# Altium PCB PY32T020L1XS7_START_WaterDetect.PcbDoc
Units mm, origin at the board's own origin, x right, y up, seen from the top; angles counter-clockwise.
Board outline 16.38 x 40.16 mm, 2 copper layers (Top Layer, Bottom Layer); 15 components, 16 nets, 48 pads, 33 vias.
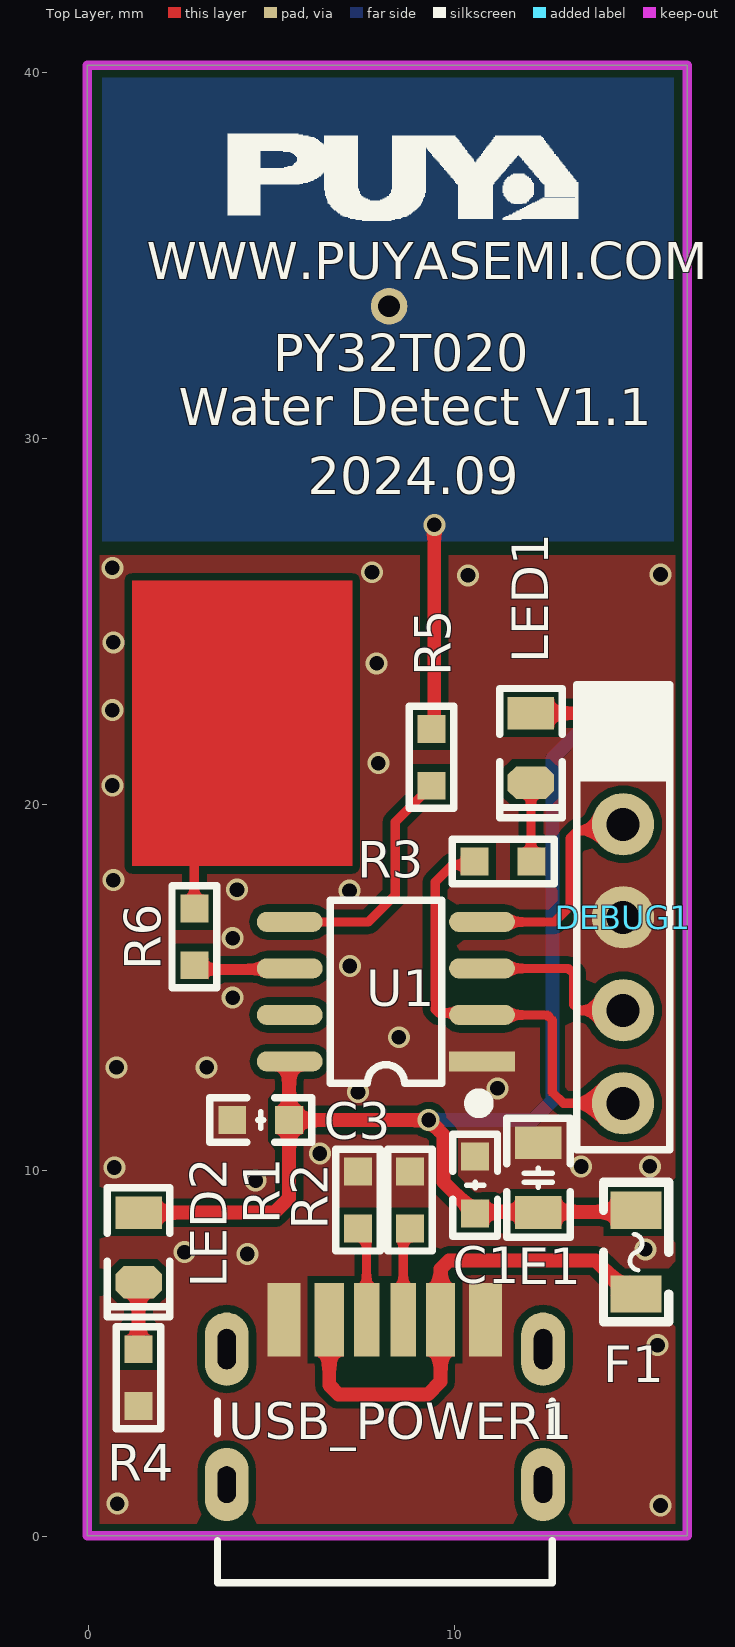
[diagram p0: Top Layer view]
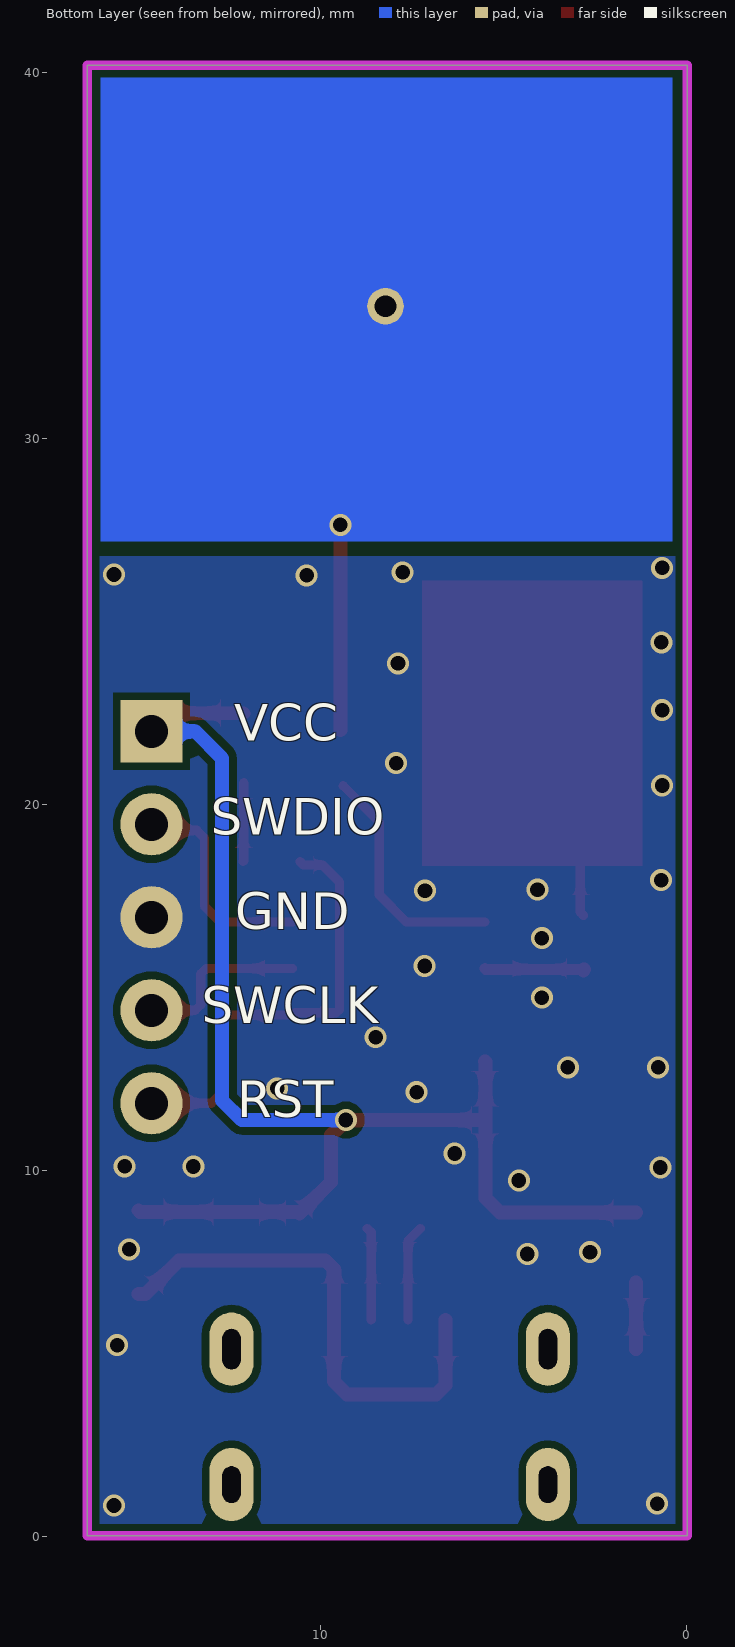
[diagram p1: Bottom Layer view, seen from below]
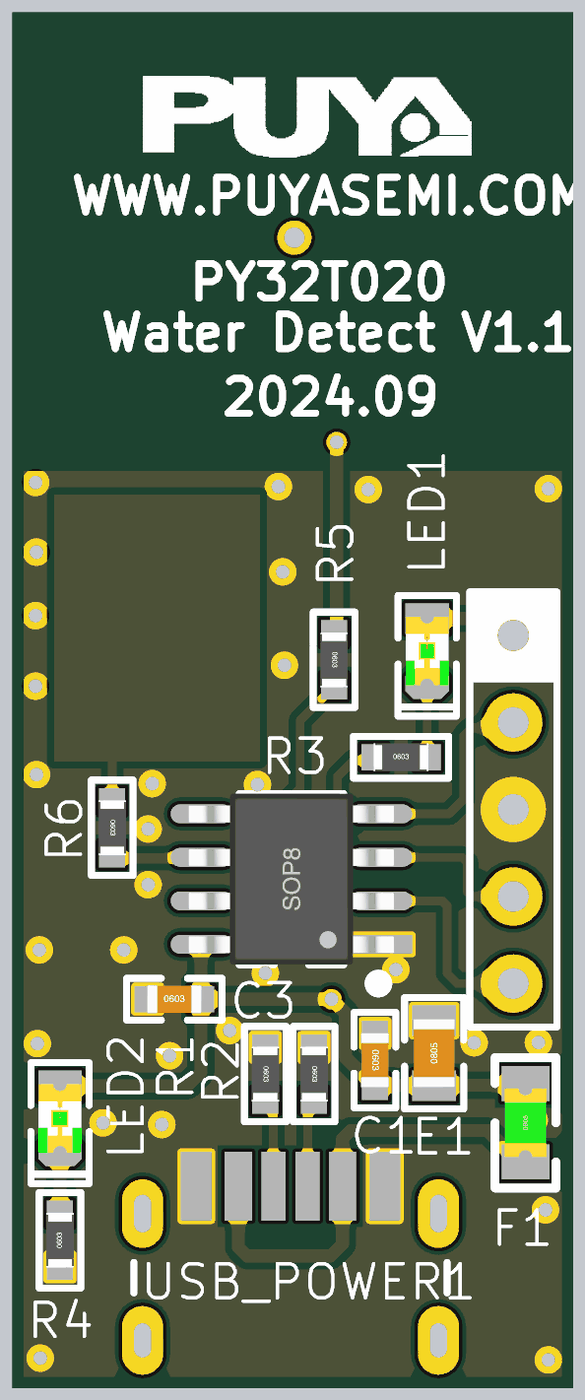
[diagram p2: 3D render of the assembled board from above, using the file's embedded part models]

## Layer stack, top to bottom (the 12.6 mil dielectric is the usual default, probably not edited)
Top Solder: solder mask 0.0102, Solder Resist, Dk 3.5
Top Layer: signal copper 0.0356
Dielectric 1: dielectric 0.32, FR-4, Dk 4.8
Bottom Layer: signal copper 0.0356
Bottom Solder: solder mask 0.0102, Solder Resist, Dk 3.5

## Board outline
-0.025,0.025 16.358,0.025 16.358,40.183 -0.025,40.183

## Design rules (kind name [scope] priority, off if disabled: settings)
Clearance Clearance_1 [All] p1: gap=0.2 ignorepadtopadclearanceinfootprint=FALSE
PlaneConnect [All] p1: planeconnectstyle=Direct reliefexpansion=0.508 reliefentries=4 reliefconductorwidth=0.254 reliefairgap=0.254
PolygonConnect [All] p1: connectstyle=Direct reliefconductorwidth=0.254 reliefentries=4 polygonreliefangle="90 Angle" airgapwidth=0.254
RoutingVias [All] p1: holewidth=0.711 width=1.27 viastyle="Through Hole" minholewidth=0.711 minwidth=1.27 maxholewidth=0.711 maxwidth=1.27
SolderMaskExpansion [All] p1: expansion=0.102 istentingtop=FALSE
SupplyNets "Schematic Supply Nets_2" [InNet('VCC')] p1: voltage=0.000
SupplyNets "Schematic Supply Nets_1" [InNet('GND')] p2: voltage=0.000
SupplyNets "Schematic Supply Nets" [InNet('VBUS')] p3: voltage=0.000
Width [All] p1: maxlimit=0.6 minlimit=0.254 preferedwidth=0.254
29 further rules are at their usual default settings.

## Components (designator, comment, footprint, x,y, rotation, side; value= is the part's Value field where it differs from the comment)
C1 "104" "C 0603_L" 10.566,9.601 r270 top
C3 "104" "C 0603_L" 4.709,11.379 r0 top
DEBUG1 "ISP" ISP_DIP_2.54_5P 14.605,21.996 r270 top
E1 "10uF/10V" "C 0805_L" 12.294,9.804 r90 top
F1 "500ma" "FU 0805" 14.961,7.772 r90 top
LED1 "红色" "LED 0805R" 12.09,21.539 r270 top
LED2 "红色" "LED 0805R" 1.372,7.899 r270 top
R1 "5.1K" "R 0603_L" 7.366,9.195 r270 top
R2 "5.1K" "R 0603_L" 8.788,9.195 r270 top
R3 "1K" "R 0603_L" 11.328,18.44 r0 top
R4 "1K" "R 0603_L" 1.372,4.343 r90 top
R5 "1K" "R 0603_L" 9.373,21.285 r270 top
R6 "1K" "R 0603_L" 2.896,16.383 r270 top
U1 "PY32T020L1XS7" SOP8_N 8.128,14.884 r180 top
USB_POWER1 "USB-C" USB-C/S_C 8.101,-1.128 r0 top

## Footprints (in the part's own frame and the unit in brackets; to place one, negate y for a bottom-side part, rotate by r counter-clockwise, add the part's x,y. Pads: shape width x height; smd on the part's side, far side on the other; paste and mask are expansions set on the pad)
"C 0603_L" [mil] "无极性贴片电容"
  rect 30x30 smd: 1(-30.59,0) 2(30.59,0)
  silkscreen extent -55,-24 55,24, body extent -31,-16 31,16, height 32
"C 0805_L" [mil] "无极性贴片电容"
  rect 35x50 smd: 1(-37.4,0) 2(37.4,0)
  silkscreen extent -64,-34 64,34, body extent -39,-24 39,24, height 20
"FU 0805" [mil] "贴片保险丝"
  rect 40x55 smd: 1(-45,0) 2(45,0)
  silkscreen extent -75,-35 75,35, body extent -39,-24 39,24, height 20
ISP_DIP_2.54_5P [mm] "5P 下载端口"
  rect 1.7x1.7 hole 0.9: 1(0,0)
  round 1.7 hole 0.9: 2(2.54,0) 3(5.08,0) 4(7.62,0) 5(10.16,0)
  silkscreen extent -1.27,-1.27 11.43,1.27
"LED 0805R" [mil] "红色0805LED"
  rect 35x50 smd: 1(-37.41,0)
  oct 35x50 smd: 2(37.4,0)
  silkscreen extent -64,-33 75,33, body extent -39,-25 39,25, height 32
"R 0603_L" [mil] "1/10W贴片电阻"
  rect 30x30 smd: 1(-30.59,0) 2(30.59,0)
  silkscreen extent -55,-24 55,24, body extent -31,-16 32,16, height 16
SOP8_N [mm] "5*6*1.8mm（长宽高）"
  rect 1.8x0.55 smd: 1(-2.625,1.905)
  oval 1.8x0.55 smd: 2(-2.625,0.635) 3(-2.625,-0.635) 4(-2.625,-1.905) 5(2.625,-1.905) 6(2.625,-0.635) 7(2.625,0.635) 8(2.625,1.905)
  silkscreen extent -2.69,-2.5 1.52,3.2, body extent -3,-2.5 3,2.5, height 1.9
USB-C/S_C [mm] "Type-C 6P母座"
  oval 1.2x2 hole 0.5 slot 1 at 90 deg: 0(-4.32,2.55) 0(4.32,2.55)
  oval 1.2x2 hole 0.5 slot 1.1 at 90 deg: 0(-4.32,6.25) 0(4.32,6.25)
  rect 0.7x2 smd: A5(-0.5,7.05) B5(0.5,7.05)
  rect 0.8x2 smd: A9(1.52,7.05) B9(-1.52,7.05)
  rect 0.9x2 smd: A12(2.75,7.05) B12(-2.75,7.05)
  silkscreen extent -4.57,-0.13 4.57,4.83, body extent -4.47,0 4.48,7.05, height 3.16

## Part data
C1 C3: library part C, "无极性贴片电容"
DEBUG1: library part ISP_5Pin, "程序下载端口"
E1: library part C-CM, "贴片电解电容"
F1: library part FU, "贴片保险丝"
LED1 LED2: library part LED-SMD, "贴片LED"
R1 R2: library part R
R3 R4 R5 R6: library part R, "贴片电阻"
USB_POWER1: library part USB-C_6P/S, "USB-C_6P型母接口"

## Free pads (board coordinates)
  round 1 hole 0.6: 2(8.215,33.604)

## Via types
v1: diameter 0.6, hole 0.4, Top Layer to Bottom Layer, 33 vias

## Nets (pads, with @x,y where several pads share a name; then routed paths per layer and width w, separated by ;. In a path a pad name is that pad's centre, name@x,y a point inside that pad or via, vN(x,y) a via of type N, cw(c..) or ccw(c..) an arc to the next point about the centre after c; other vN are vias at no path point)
GND: C1.1 C3.1 DEBUG1.3 E1.2 R1.1 R2.1 R4.1 U1.1 USB_POWER1.A12 USB_POWER1.B12
  other v1: 15.628,0.854 0.795,0.904 15.545,5.232 4.343,7.722 2.628,7.77 15.215,7.849 4.572,9.728 0.711,10.084 13.462,10.109 15.338,10.114 6.325,10.465 7.366,12.141 11.176,12.243 0.769,12.817 3.233,12.817 8.484,13.64 3.944,14.722 7.145,15.586 3.944,16.348 7.136,17.645 4.062,17.671 0.686,17.932 0.659,20.515 7.923,21.125 0.659,22.573 7.874,23.851 0.684,24.427 10.371,26.254 15.628,26.279 7.747,26.34 0.659,26.459
NetC1_2: 
NetLED1_2: LED1.2 R3.2 | length 2.2
  Top Layer w0.254: LED1.2 12.09,18.455 R3.2
NetLED2_2: LED2.2 R4.2 | length 1.8
  Top Layer w0.381: R4.2 LED2.2
NetR1_2: R1.2 USB_POWER1.A5 | length 2.6
  Top Layer w0.254: R1.2@7.264,8.418 7.601,8.082 USB_POWER1.A5
NetR2_2: R2.2 USB_POWER1.B5 | length 2.5
  Top Layer w0.254: USB_POWER1.B5 8.601,8.306 R2.2@8.712,8.418
NetR5_1: pad.2 R5.1 | length 5.6
  Top Layer w0.381: R5.1@9.449,22.037 v1(9.449,27.635)
NRST: DEBUG1.5 R3.1 U1.2 | length 12.1
  Top Layer w0.254: R3.1 10.457,18.346 9.938,18.346 9.474,17.882 9.474,14.398 9.566,14.306 10.696,14.306 U1.2 12.526,14.249 12.675,14.101 12.675,12.138 12.976,11.836 DEBUG1.5
REF: 
REF_CHS: R6.2 U1.6 | length 2.8
  Top Layer w0.3: R6.2@2.789,15.489 2.794,15.494 5.478,15.494 U1.6
  Top Layer w0.381: R6.2@2.789,15.489 R6.2@2.809,15.469
REF_PAD: R6.1 | length 2.5
  Top Layer w0.254: R6.1@2.809,16.967 2.896,17.054 2.896,19.431
SWCLK: DEBUG1.4 U1.3 | length 4.8
  Top Layer w0.254: U1.3 13.11,15.519 13.259,15.371 13.259,14.525 13.408,14.376 DEBUG1.4
SWDIO: DEBUG1.2 U1.4 | length 6
  Top Layer w0.254: U1.4 12.725,16.789 13.157,17.221 13.157,19.075 13.374,19.292 14.441,19.292 DEBUG1.2
VBUS: F1.1 USB_POWER1.A9 USB_POWER1.B9 | length 14
  Top Layer w0.381: USB_POWER1.B9 6.581,4.138 6.833,3.886 9.271,3.886 9.621,4.236 USB_POWER1.A9 9.621,7.309 9.855,7.544 13.856,7.544 14.77,6.629 F1.1
VCC: C1.2 C3.2 DEBUG1.1 E1.1 F1.2 LED1.1 LED2.1 U1.8 | length 37.5
  Top Layer w0.381: LED2.1 5.09,8.85 5.486,9.246 C3.2 ; U1.8 5.486,12.963 C3.2 ; LED1.1 14.605,22.489 DEBUG1.1 ; F1.2 14.915,8.87 10.612,8.87 C1.2 9.703,9.688 9.703,10.973 v1(9.296,11.379) C3.2
  Bottom Layer w0.381: v1(9.296,11.379) 12.141,11.379 12.675,11.913 12.675,21.26 13.407,21.992 14.6,21.992 DEBUG1.1
WATER_CHS: R5.2 U1.5 | length 6.6
  Top Layer w0.254: U1.5 7.645,16.789 8.382,17.526 8.382,19.518 R5.2
pads on no net: U1.7 USB_POWER1.0

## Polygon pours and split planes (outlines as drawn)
GND on Bottom Layer "GND_L02_P001" (solid, pour order 1): 0,0 16.383,0 16.383,26.772 0.025,26.772
GND on Top Layer "GND_L01_P002" (solid, pour order 2): -0.025,0.178 -0.025,26.721 0.051,26.797 16.307,26.797 16.383,26.721 16.307,26.645 16.307,0.051

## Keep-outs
Keep-Out Layer:
  the board outline again, w0.254

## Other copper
Top Layer:
  rectangle net REF_PAD: 1.194,18.313 7.214,26.111
Bottom Layer:
  rectangle net NetR5_1: 0.381,27.178 16.002,39.853

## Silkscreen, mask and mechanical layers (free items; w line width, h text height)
Top Overlay:
  drawing of 447 lines, arcs and shapes, not listed
  text "WWW.PUYASEMI.COM" at 1.6,34.341 h1.02
  text "PY32T020" at 5.055,31.826 h1.02
  text "Water Detect V1.1" at 2.464,30.353 h1.02
  text "2024.09" at 5.994,28.473 h1.02
Bottom Overlay:
  text "VCC" at 12.341,21.738 h1
  text "SWDIO" at 12.993,19.166 h1
  text "GND" at 12.317,16.594 h1
  text "SWCLK" at 13.233,14.023 h1
  text "RST" at 12.264,11.451 h1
